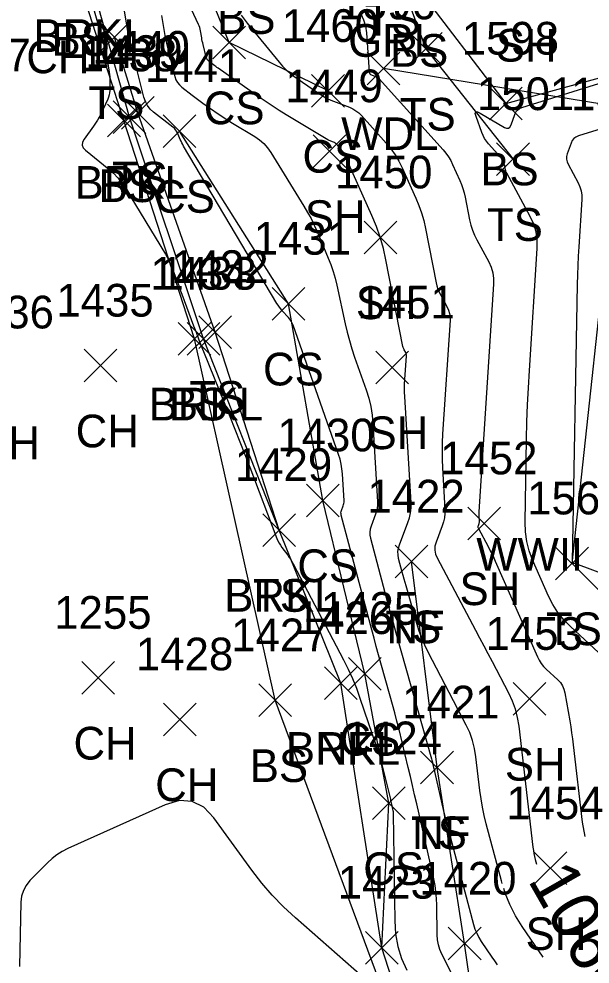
# Model space of a CAD drawing. Extents: x 1592612 to 1596497, y 111838 to 113741.
# Drawn here: x 1592890.9 to 1592925.8, y 113362.1 to 113419.9 of the extents above; entities that cross this region are included whole.
import ezdxf

# ---------------------------------------------------------------- set-up
doc = ezdxf.new("R2010")
doc.units = 0
for name, color, linetype in [('L_A', 7, 'Continuous'), ('L_C', 7, 'Continuous'), ('L_I', 7, 'Continuous'), ('L_TIC', 7, 'Continuous'), ('LAWA', 7, 'Continuous'), ('LAWE', 7, 'Continuous'), ('LELB', 7, 'Continuous'), ('LSOGCMA', 7, 'Continuous'), ('LSOGCMA_T', 7, 'Continuous'), ('LSOGCMI', 7, 'Continuous'), ('R_A', 7, 'Continuous')]:
    doc.layers.add(name, color=color, linetype=linetype)

msp = doc.modelspace()

# ---------------------------------------------------------------- linework, layer by layer
at = {"layer": 'L_TIC'}
for points in [[(1592895.764, 113417.792), (1592897.764, 113419.792)], [(1592897.764, 113417.792), (1592895.764, 113419.792)], [(1592902.782, 113417.472), (1592904.782, 113419.472)], [(1592904.782, 113417.472), (1592902.782, 113419.472)], [(1592914.797, 113417.084), (1592916.797, 113419.084)], [(1592916.797, 113417.084), (1592914.797, 113419.084)], [(1592912.205, 113415.891), (1592914.205, 113417.891)], [(1592914.205, 113415.891), (1592912.205, 113417.891)], [(1592908.817, 113414.507), (1592910.817, 113416.507)], [(1592910.817, 113414.507), (1592908.817, 113416.507)], [(1592897.198, 113413.176), (1592899.198, 113415.176)], [(1592899.198, 113413.176), (1592897.198, 113415.176)], [(1592919.685, 113413.734), (1592921.685, 113415.734)], [(1592921.685, 113413.734), (1592919.685, 113415.734)], [(1592896.345, 113412.71), (1592898.345, 113414.71)], [(1592898.345, 113412.71), (1592896.345, 113414.71)], [(1592896.68, 113412.914), (1592898.68, 113414.914)], [(1592898.68, 113412.914), (1592896.68, 113414.914)], [(1592899.746, 113412.057), (1592901.746, 113414.057)], [(1592901.746, 113412.057), (1592899.746, 113414.057)], [(1592908.914, 113410.819), (1592910.914, 113412.819)], [(1592910.914, 113410.819), (1592908.914, 113412.819)], [(1592920.128, 113410.337), (1592922.128, 113412.337)], [(1592922.128, 113410.337), (1592920.128, 113412.337)], [(1592912.03, 113405.547), (1592914.03, 113407.547)], [(1592914.03, 113405.547), (1592912.03, 113407.547)], [(1592906.403, 113401.492), (1592908.403, 113403.492)], [(1592908.403, 113401.492), (1592906.403, 113403.492)], [(1592900.65, 113399.349), (1592902.65, 113401.349)], [(1592902.65, 113399.349), (1592900.65, 113401.349)], [(1592901.208, 113399.349), (1592903.208, 113401.349)], [(1592903.208, 113399.349), (1592901.208, 113401.349)], [(1592901.926, 113399.759), (1592903.926, 113401.759)], [(1592903.926, 113399.759), (1592901.926, 113401.759)], [(1592894.902, 113397.704), (1592896.902, 113399.704)], [(1592896.902, 113397.704), (1592894.902, 113399.704)], [(1592912.742, 113397.594), (1592914.742, 113399.594)], [(1592914.742, 113397.594), (1592912.742, 113399.594)], [(1592908.499, 113389.458), (1592910.499, 113391.458)], [(1592910.499, 113389.458), (1592908.499, 113391.458)], [(1592918.367, 113388.051), (1592920.367, 113390.051)], [(1592920.367, 113388.051), (1592918.367, 113390.051)], [(1592905.825, 113387.644), (1592907.825, 113389.644)], [(1592907.825, 113387.644), (1592905.825, 113389.644)], [(1592905.825, 113387.644), (1592907.825, 113389.644)], [(1592907.825, 113387.644), (1592905.825, 113389.644)], [(1592913.915, 113385.717), (1592915.915, 113387.717)], [(1592915.915, 113385.717), (1592913.915, 113387.717)], [(1592913.915, 113385.717), (1592915.915, 113387.717)], [(1592915.915, 113385.717), (1592913.915, 113387.717)], [(1592923.735, 113385.602), (1592925.735, 113387.602)], [(1592925.735, 113385.602), (1592923.735, 113387.602)], [(1592894.773, 113378.603), (1592896.773, 113380.603)], [(1592896.773, 113378.603), (1592894.773, 113380.603)], [(1592911.075, 113378.848), (1592913.075, 113380.848)], [(1592913.075, 113378.848), (1592911.075, 113380.848)], [(1592909.596, 113378.281), (1592911.596, 113380.281)], [(1592911.596, 113378.281), (1592909.596, 113380.281)], [(1592909.596, 113378.281), (1592911.596, 113380.281)], [(1592911.596, 113378.281), (1592909.596, 113380.281)], [(1592921.14, 113377.314), (1592923.14, 113379.314)], [(1592923.14, 113377.314), (1592921.14, 113379.314)], [(1592905.593, 113377.229), (1592907.593, 113379.229)], [(1592907.593, 113377.229), (1592905.593, 113379.229)], [(1592899.766, 113376.061), (1592901.766, 113378.061)], [(1592901.766, 113376.061), (1592899.766, 113378.061)], [(1592915.481, 113373.12), (1592917.481, 113375.12)], [(1592917.481, 113373.12), (1592915.481, 113375.12)], [(1592915.481, 113373.12), (1592917.481, 113375.12)], [(1592917.481, 113373.12), (1592915.481, 113375.12)], [(1592912.529, 113370.926), (1592914.529, 113372.926)], [(1592914.529, 113370.926), (1592912.529, 113372.926)], [(1592922.41, 113366.949), (1592924.41, 113368.949)], [(1592924.41, 113366.949), (1592922.41, 113368.949)], [(1592917.171, 113362.34), (1592919.171, 113364.34)], [(1592919.171, 113362.34), (1592917.171, 113364.34)], [(1592912.1, 113362.091), (1592914.1, 113364.091)], [(1592914.1, 113362.091), (1592912.1, 113364.091)], [(1592912.1, 113362.091), (1592914.1, 113364.091)], [(1592914.1, 113362.091), (1592912.1, 113364.091)]]:
    msp.add_lwpolyline(points, dxfattribs=at)
at = {"layer": 'LAWA'}
msp.add_lwpolyline([(1592932.916, 113413.656), (1592913.205, 113416.891)], dxfattribs=at)
at = {"layer": 'LAWE'}
msp.add_lwpolyline([(1593001.92, 113269.875), (1592980.168, 113281.757), (1592972.077, 113292.77), (1592952.739, 113309.006), (1592930.405, 113333.014), (1592916.015, 113354.051), (1592913.1, 113363.091), (1592910.596, 113379.281), (1592906.825, 113388.644), (1592902.208, 113400.349), (1592897.68, 113413.914), (1592895.157, 113422.89), (1592891.073, 113425.248), (1592889.456, 113425.542), (1592888.74, 113438.019), (1592887.745, 113444.76), (1592887.496, 113453.354)], dxfattribs=at)
at = {"layer": 'LELB'}
for points in [[(1592909.817, 113415.507), (1592903.782, 113418.472), (1592899.758, 113428.347), (1592891.065, 113434.312)], [(1592908.536, 113430.778), (1592913.657, 113423.892), (1592915.797, 113418.084), (1592921.128, 113411.337)], [(1593000.607, 113268.02), (1592979.237, 113281.269), (1592969.817, 113290.666), (1592952.505, 113308.706), (1592930.32, 113332.83), (1592915.558, 113354.032), (1592906.593, 113378.229), (1592901.651, 113400.349), (1592897.345, 113413.71), (1592894.471, 113422.658), (1592891.543, 113424.972)], [(1592915.162, 113421.985), (1592920.685, 113414.734), (1592932.512, 113417.98), (1592943.04, 113416.389)], [(1592906.825, 113388.644), (1592902.926, 113400.759), (1592898.198, 113414.176), (1592896.764, 113418.792)], [(1593022.223, 113298.621), (1592996.05, 113319.251), (1592973.737, 113329.884), (1592951.567, 113338.734), (1592939.58, 113363.449), (1592930.763, 113371.375), (1592929.879, 113381.446), (1592924.735, 113386.602), (1592927.418, 113411.322), (1592932.961, 113414.131), (1592945.073, 113412.416), (1592963.598, 113404.825), (1592977.398, 113399.854), (1592996.446, 113393.062), (1593007.402, 113387.97)], [(1592913.1, 113363.091), (1592913.529, 113371.926), (1592912.075, 113379.848), (1592909.499, 113390.459), (1592907.403, 113402.492), (1592900.746, 113413.057)], [(1593002.844, 113271.334), (1592982.233, 113284.253), (1592973.366, 113294.033), (1592954.604, 113311.113), (1592933.333, 113334.792), (1592919.468, 113354.266), (1592918.171, 113363.34), (1592916.481, 113374.12), (1592914.915, 113386.717)]]:
    msp.add_lwpolyline(points, dxfattribs=at)
at = {"layer": 'LSOGCMA'}
for points in [[(1592904.499, 113420.148), (1592904.88, 113419.661), (1592906.836, 113417.26), (1592907.038, 113417.027), (1592907.255, 113416.811), (1592907.487, 113416.609), (1592907.733, 113416.423), (1592909.113, 113415.451), (1592909.182, 113415.403), (1592909.253, 113415.357), (1592909.324, 113415.311), (1592909.396, 113415.267), (1592909.685, 113415.093), (1592909.759, 113415.052), (1592909.833, 113415.013), (1592909.91, 113414.978), (1592909.988, 113414.946), (1592911.122, 113414.509), (1592911.329, 113414.415), (1592911.522, 113414.299), (1592911.699, 113414.161), (1592911.861, 113414.001), (1592913.378, 113412.319), (1592913.667, 113411.972), (1592913.927, 113411.605), (1592914.157, 113411.22), (1592914.358, 113410.815), (1592915.19, 113408.958), (1592915.378, 113408.506), (1592915.538, 113408.045), (1592915.672, 113407.576), (1592915.78, 113407.099), (1592916.43, 113403.778), (1592916.477, 113403.577), (1592916.54, 113403.381), (1592916.617, 113403.19), (1592916.708, 113403.005), (1592917.105, 113402.274), (1592917.19, 113402.088), (1592917.247, 113401.896), (1592917.276, 113401.698), (1592917.277, 113401.494), (1592916.822, 113394.504), (1592916.797, 113393.993), (1592916.788, 113393.481), (1592916.794, 113392.97), (1592916.816, 113392.458), (1592916.966, 113389.919), (1592916.968, 113389.656), (1592916.942, 113389.398), (1592916.888, 113389.143), (1592916.806, 113388.893), (1592916.423, 113387.902), (1592916.355, 113387.656), (1592916.342, 113387.414), (1592916.384, 113387.174), (1592916.481, 113386.938), (1592918.834, 113382.523), (1592919.088, 113382.044), (1592919.341, 113381.566), (1592919.593, 113381.087), (1592919.844, 113380.607), (1592920.846, 113378.687), (1592921.073, 113378.2), (1592921.254, 113377.698), (1592921.387, 113377.182), (1592921.474, 113376.652), (1592922.347, 113369.232), (1592922.373, 113369.045), (1592922.405, 113368.859), (1592922.443, 113368.674), (1592922.489, 113368.491), (1592922.563, 113368.21)], [(1592912.412, 113360.878), (1592907.821, 113364.914), (1592907.097, 113365.588), (1592906.413, 113366.298), (1592905.77, 113367.046), (1592905.167, 113367.83), (1592902.839, 113371.042), (1592902.217, 113371.694), (1592901.514, 113372.043), (1592900.73, 113372.09), (1592899.866, 113371.834), (1592893.905, 113369.151), (1592893.566, 113368.979), (1592893.247, 113368.778), (1592892.949, 113368.548), (1592892.671, 113368.289), (1592891.599, 113367.193), (1592891.364, 113366.906), (1592891.193, 113366.591), (1592891.087, 113366.249), (1592891.045, 113365.88), (1592890.951, 113361.938)]]:
    msp.add_lwpolyline(points, dxfattribs=at)
at = {"layer": 'LSOGCMI'}
for points in [[(1592920.473, 113367.017), (1592920.424, 113367.173), (1592919.494, 113370.672), (1592919.37, 113371.175), (1592919.264, 113371.681), (1592919.176, 113372.191), (1592919.106, 113372.705), (1592918.864, 113374.766), (1592918.781, 113375.274), (1592918.653, 113375.769), (1592918.48, 113376.249), (1592918.262, 113376.716), (1592915.938, 113381.17), (1592915.731, 113381.593), (1592915.546, 113382.026), (1592915.384, 113382.467), (1592915.244, 113382.918), (1592914.591, 113385.228), (1592914.533, 113385.438), (1592914.475, 113385.648), (1592914.417, 113385.858), (1592914.361, 113386.069), (1592914.137, 113386.911), (1592914.097, 113387.121), (1592914.092, 113387.329), (1592914.12, 113387.535), (1592914.182, 113387.739), (1592914.706, 113389.096), (1592914.803, 113389.392), (1592914.867, 113389.694), (1592914.898, 113390), (1592914.896, 113390.312), (1592914.512, 113396.824), (1592914.5, 113397.083), (1592914.497, 113397.341), (1592914.502, 113397.599), (1592914.515, 113397.857), (1592914.609, 113399.305), (1592914.609, 113399.355), (1592914.601, 113399.404), (1592914.588, 113399.451), (1592914.567, 113399.497), (1592914.469, 113399.676), (1592914.447, 113399.721), (1592914.428, 113399.768), (1592914.413, 113399.816), (1592914.401, 113399.865), (1592913.36, 113405.182), (1592913.204, 113405.875), (1592913.009, 113406.556), (1592912.776, 113407.225), (1592912.504, 113407.881), (1592910.832, 113411.611), (1592910.791, 113411.695), (1592910.743, 113411.775), (1592910.689, 113411.85), (1592910.629, 113411.922), (1592910.316, 113412.27), (1592910.283, 113412.303), (1592910.246, 113412.331), (1592910.206, 113412.355), (1592910.163, 113412.375), (1592909.985, 113412.443), (1592909.941, 113412.461), (1592909.898, 113412.481), (1592909.856, 113412.503), (1592909.815, 113412.527), (1592907.267, 113414.056), (1592906.831, 113414.323), (1592906.401, 113414.597), (1592905.975, 113414.88), (1592905.555, 113415.17), (1592903.096, 113416.901), (1592903.027, 113416.951), (1592902.957, 113417.001), (1592902.889, 113417.053), (1592902.821, 113417.105), (1592902.55, 113417.315), (1592902.488, 113417.371), (1592902.438, 113417.435), (1592902.4, 113417.507), (1592902.373, 113417.586), (1592902.181, 113418.341), (1592902.156, 113418.444), (1592902.133, 113418.548), (1592902.113, 113418.652), (1592902.095, 113418.757), (1592902.028, 113419.177), (1592902.008, 113419.281), (1592901.98, 113419.383), (1592901.946, 113419.483), (1592901.905, 113419.58), (1592898.668, 113426.542)], [(1592894.91, 113422.601), (1592896.168, 113418.115), (1592896.213, 113417.944), (1592896.253, 113417.773), (1592896.289, 113417.601), (1592896.319, 113417.427), (1592896.442, 113416.661), (1592896.461, 113416.522), (1592896.474, 113416.382), (1592896.481, 113416.242), (1592896.482, 113416.102), (1592896.473, 113415.539), (1592896.464, 113415.401), (1592896.44, 113415.265), (1592896.402, 113415.133), (1592896.349, 113415.004), (1592895.923, 113414.097), (1592895.827, 113413.906), (1592895.723, 113413.72), (1592895.611, 113413.539), (1592895.49, 113413.363), (1592894.909, 113412.56), (1592894.81, 113412.374), (1592894.792, 113412.199), (1592894.855, 113412.034), (1592894.998, 113411.879), (1592896.417, 113410.728), (1592896.702, 113410.475), (1592896.962, 113410.201), (1592897.198, 113409.906), (1592897.409, 113409.589), (1592899.875, 113405.524), (1592899.985, 113405.333), (1592900.086, 113405.137), (1592900.178, 113404.938), (1592900.261, 113404.733), (1592900.574, 113403.907), (1592900.652, 113403.7), (1592900.729, 113403.494), (1592900.806, 113403.287), (1592900.883, 113403.08), (1592901.602, 113401.135), (1592901.749, 113400.743), (1592901.898, 113400.351), (1592902.051, 113399.961), (1592902.206, 113399.572), (1592903.814, 113395.59), (1592904.123, 113394.818), (1592904.429, 113394.044), (1592904.731, 113393.27), (1592905.029, 113392.493), (1592906.698, 113388.117), (1592906.757, 113387.976), (1592906.826, 113387.841), (1592906.904, 113387.711), (1592906.992, 113387.586), (1592907.361, 113387.098), (1592907.451, 113386.974), (1592907.535, 113386.847), (1592907.614, 113386.717), (1592907.688, 113386.583), (1592910.763, 113380.709), (1592911.049, 113380.136), (1592911.313, 113379.554), (1592911.554, 113378.962), (1592911.772, 113378.36), (1592912.791, 113375.378), (1592912.9, 113375.049), (1592913, 113374.717), (1592913.093, 113374.384), (1592913.178, 113374.048), (1592913.629, 113372.18), (1592913.647, 113372.104), (1592913.665, 113372.028), (1592913.683, 113371.951), (1592913.7, 113371.875), (1592913.769, 113371.57), (1592913.784, 113371.493), (1592913.795, 113371.416), (1592913.803, 113371.339), (1592913.806, 113371.261), (1592913.895, 113364.728), (1592913.949, 113363.94), (1592914.091, 113363.174), (1592914.32, 113362.429), (1592914.637, 113361.706)], [(1592917.351, 113361.582), (1592916.786, 113362.699), (1592916.662, 113362.983), (1592916.572, 113363.275), (1592916.516, 113363.575), (1592916.495, 113363.884), (1592916.47, 113365.694), (1592916.454, 113366.099), (1592916.417, 113366.501), (1592916.359, 113366.901), (1592916.28, 113367.298), (1592915.239, 113371.893), (1592915.112, 113372.451), (1592914.982, 113373.008), (1592914.851, 113373.565), (1592914.718, 113374.122), (1592914.16, 113376.433), (1592914.034, 113376.945), (1592913.903, 113377.456), (1592913.767, 113377.965), (1592913.626, 113378.474), (1592913.053, 113380.504), (1592912.91, 113381.012), (1592912.77, 113381.521), (1592912.631, 113382.03), (1592912.495, 113382.539), (1592910.625, 113389.561), (1592910.612, 113389.634), (1592910.61, 113389.706), (1592910.619, 113389.778), (1592910.641, 113389.849), (1592910.75, 113390.131), (1592910.773, 113390.202), (1592910.789, 113390.275), (1592910.796, 113390.348), (1592910.796, 113390.423), (1592910.698, 113392.085), (1592910.67, 113392.385), (1592910.621, 113392.68), (1592910.551, 113392.972), (1592910.461, 113393.26), (1592907.678, 113401.18), (1592907.626, 113401.309), (1592907.562, 113401.43), (1592907.486, 113401.544), (1592907.399, 113401.651), (1592907.025, 113402.066), (1592906.935, 113402.172), (1592906.849, 113402.282), (1592906.77, 113402.396), (1592906.696, 113402.514), (1592900.992, 113412.127), (1592900.935, 113412.225), (1592900.883, 113412.325), (1592900.833, 113412.427), (1592900.787, 113412.531), (1592900.609, 113412.948), (1592900.559, 113413.048), (1592900.497, 113413.139), (1592900.424, 113413.222), (1592900.341, 113413.296), (1592899.159, 113414.214), (1592898.952, 113414.403), (1592898.783, 113414.617), (1592898.654, 113414.857), (1592898.564, 113415.123), (1592897.837, 113417.986), (1592897.744, 113418.37), (1592897.66, 113418.756), (1592897.585, 113419.143), (1592897.518, 113419.532), (1592897.238, 113421.281)], [(1592899.648, 113420.135), (1592899.807, 113419.145), (1592899.849, 113418.898), (1592899.897, 113418.652), (1592899.95, 113418.407), (1592900.009, 113418.163), (1592900.461, 113416.385), (1592900.524, 113416.198), (1592900.615, 113416.029), (1592900.733, 113415.878), (1592900.879, 113415.745), (1592901.517, 113415.25), (1592901.677, 113415.127), (1592901.839, 113415.006), (1592902.002, 113414.887), (1592902.166, 113414.769), (1592903.107, 113414.107), (1592903.32, 113413.96), (1592903.535, 113413.817), (1592903.753, 113413.678), (1592903.974, 113413.543), (1592905.349, 113412.717), (1592905.637, 113412.521), (1592905.896, 113412.294), (1592906.126, 113412.037), (1592906.326, 113411.751), (1592908.349, 113408.457), (1592908.571, 113408.08), (1592908.778, 113407.696), (1592908.97, 113407.303), (1592909.146, 113406.903), (1592909.823, 113405.288), (1592909.982, 113404.881), (1592910.123, 113404.468), (1592910.245, 113404.049), (1592910.348, 113403.624), (1592910.865, 113401.262), (1592910.986, 113400.746), (1592911.123, 113400.233), (1592911.276, 113399.725), (1592911.444, 113399.222), (1592912.148, 113397.217), (1592912.306, 113396.712), (1592912.428, 113396.2), (1592912.514, 113395.68), (1592912.563, 113395.153), (1592912.846, 113390.368), (1592912.847, 113390.174), (1592912.828, 113389.984), (1592912.788, 113389.797), (1592912.728, 113389.613), (1592912.446, 113388.884), (1592912.391, 113388.701), (1592912.366, 113388.517), (1592912.371, 113388.33), (1592912.406, 113388.142), (1592913.291, 113384.818), (1592913.456, 113384.201), (1592913.624, 113383.585), (1592913.794, 113382.969), (1592913.967, 113382.355), (1592916.146, 113374.638), (1592916.163, 113374.574), (1592916.181, 113374.509), (1592916.197, 113374.445), (1592916.213, 113374.38), (1592916.276, 113374.12), (1592916.291, 113374.056), (1592916.306, 113373.991), (1592916.322, 113373.926), (1592916.336, 113373.861), (1592916.781, 113371.898), (1592916.862, 113371.55), (1592916.945, 113371.202), (1592917.032, 113370.855), (1592917.123, 113370.509), (1592918.718, 113364.508), (1592918.803, 113364.234), (1592918.91, 113363.971), (1592919.039, 113363.718), (1592919.189, 113363.474), (1592919.834, 113362.52), (1592919.994, 113362.281), (1592920.151, 113362.04)], [(1592911.815, 113420.226), (1592911.991, 113419.862), (1592912.108, 113419.476), (1592912.167, 113419.066), (1592912.338, 113416.676), (1592912.35, 113416.614), (1592912.376, 113416.562), (1592912.418, 113416.522), (1592912.473, 113416.492), (1592912.726, 113416.395), (1592912.787, 113416.368), (1592912.843, 113416.334), (1592912.895, 113416.293), (1592912.942, 113416.246), (1592916.858, 113411.904), (1592917.029, 113411.699), (1592917.182, 113411.482), (1592917.319, 113411.254), (1592917.437, 113411.015), (1592917.877, 113410.034), (1592917.979, 113409.787), (1592918.067, 113409.535), (1592918.141, 113409.278), (1592918.2, 113409.017), (1592918.474, 113407.617), (1592918.548, 113407.3), (1592918.646, 113406.991), (1592918.767, 113406.691), (1592918.912, 113406.399), (1592919.644, 113405.051), (1592919.793, 113404.725), (1592919.893, 113404.389), (1592919.943, 113404.041), (1592919.944, 113403.682), (1592919.039, 113389.753), (1592919.036, 113389.687), (1592919.035, 113389.622), (1592919.035, 113389.556), (1592919.038, 113389.49), (1592919.058, 113389.163), (1592919.058, 113389.129), (1592919.055, 113389.096), (1592919.048, 113389.063), (1592919.037, 113389.031), (1592918.988, 113388.903), (1592918.979, 113388.871), (1592918.977, 113388.84), (1592918.983, 113388.809), (1592918.995, 113388.779), (1592919.63, 113387.587), (1592919.74, 113387.377), (1592919.845, 113387.165), (1592919.946, 113386.952), (1592920.044, 113386.736), (1592922.617, 113380.894), (1592922.724, 113380.682), (1592922.85, 113380.484), (1592922.996, 113380.3), (1592923.162, 113380.13), (1592923.867, 113379.481), (1592924.026, 113379.309), (1592924.152, 113379.119), (1592924.243, 113378.911), (1592924.301, 113378.684), (1592924.596, 113376.967), (1592924.656, 113376.602), (1592924.711, 113376.236), (1592924.761, 113375.869), (1592924.807, 113375.502), (1592925.359, 113370.776), (1592925.516, 113369.895)], [(1592926.35, 113381.157), (1592924.632, 113382.741), (1592924.227, 113383.154), (1592923.871, 113383.602), (1592923.563, 113384.084), (1592923.303, 113384.602), (1592922.323, 113386.825), (1592922.113, 113387.38), (1592921.966, 113387.948), (1592921.882, 113388.528), (1592921.862, 113389.122), (1592921.953, 113394.212), (1592921.978, 113395.26), (1592922.015, 113396.308), (1592922.065, 113397.355), (1592922.127, 113398.401), (1592922.612, 113405.871), (1592922.611, 113406.384), (1592922.538, 113406.881), (1592922.396, 113407.363), (1592922.182, 113407.829), (1592920.743, 113410.479), (1592920.718, 113410.53), (1592920.697, 113410.582), (1592920.68, 113410.636), (1592920.667, 113410.691), (1592920.619, 113410.934), (1592920.609, 113410.979), (1592920.596, 113411.024), (1592920.581, 113411.068), (1592920.563, 113411.111), (1592920.487, 113411.281), (1592920.466, 113411.323), (1592920.442, 113411.362), (1592920.416, 113411.4), (1592920.386, 113411.435), (1592919.627, 113412.278), (1592919.498, 113412.435), (1592919.387, 113412.602), (1592919.293, 113412.779), (1592919.216, 113412.967), (1592918.868, 113413.947), (1592918.823, 113414.13), (1592918.851, 113414.226), (1592918.95, 113414.235), (1592919.122, 113414.156), (1592920.603, 113413.281), (1592920.738, 113413.225), (1592920.852, 113413.231), (1592920.942, 113413.299), (1592921.01, 113413.43), (1592921.237, 113414.075), (1592921.307, 113414.222), (1592921.403, 113414.342), (1592921.526, 113414.434), (1592921.676, 113414.499), (1592932.392, 113417.85)], [(1592928.756, 113413.892), (1592925.127, 113412.757), (1592924.974, 113412.69), (1592924.847, 113412.596), (1592924.748, 113412.473), (1592924.676, 113412.321), (1592924.444, 113411.66), (1592924.404, 113411.496), (1592924.399, 113411.335), (1592924.429, 113411.176), (1592924.495, 113411.021), (1592925.108, 113409.892), (1592925.22, 113409.649), (1592925.294, 113409.397), (1592925.332, 113409.138), (1592925.333, 113408.87), (1592925.144, 113405.973), (1592925.111, 113405.399), (1592925.083, 113404.825), (1592925.063, 113404.251), (1592925.049, 113403.677), (1592924.744, 113386.698), (1592924.744, 113386.692), (1592924.746, 113386.685), (1592924.748, 113386.679), (1592924.75, 113386.673), (1592924.769, 113386.642), (1592924.772, 113386.636), (1592924.774, 113386.629), (1592924.776, 113386.627), (1592924.778, 113386.626), (1592924.874, 113386.62), (1592924.89, 113386.618), (1592924.907, 113386.615), (1592924.923, 113386.611), (1592924.938, 113386.606), (1592931.666, 113384.097)], [(1592922.965, 113362.507), (1592921.693, 113364.387), (1592921.288, 113365.043), (1592920.941, 113365.726), (1592920.653, 113366.436), (1592920.57, 113366.705)]]:
    msp.add_lwpolyline(points, dxfattribs=at)

# ---------------------------------------------------------------- texts
at = {"layer": 'L_A'}
for s, p in [('BS', (1592903.037, 113419.002)), ('TS', (1592912.066, 113418.892)), ('BRKL', (1592891.803, 113417.89)), ('BS', (1592892.912, 113417.658)), ('SH', (1592920.077, 113417.304)), ('BS', (1592913.603, 113416.986)), ('CH', (1592891.374, 113416.595)), ('TS', (1592895.173, 113413.792)), ('CS', (1592902.223, 113413.472)), ('TS', (1592914.206, 113413.084)), ('WDL', (1592910.623, 113411.891)), ('CS', (1592908.258, 113410.507)), ('BS', (1592919.126, 113409.734)), ('TS', (1592896.608, 113409.176)), ('BRKL', (1592894.326, 113408.914)), ('BS', (1592895.786, 113408.71)), ('CS', (1592899.187, 113408.057)), ('SH', (1592908.402, 113406.819)), ('TS', (1592919.537, 113406.337)), ('SH', (1592911.518, 113401.547)), ('CS', (1592905.844, 113397.492)), ('BRKL', (1592898.854, 113395.349)), ('BS', (1592900.091, 113395.349)), ('TS', (1592901.335, 113395.759)), ('CH', (1592894.391, 113393.704)), ('SH', (1592912.23, 113393.594)), ('CH', (1592888.347, 113392.98)), ('CS', (1592907.94, 113385.458)), ('TS', (1592905.235, 113383.644)), ('SH', (1592917.855, 113384.051)), ('BRKL', (1592903.471, 113383.644)), ('TS', (1592913.325, 113381.717)), ('NF', (1592913.396, 113381.717)), ('TS', (1592923.144, 113381.602)), ('CH', (1592894.261, 113374.603)), ('CS', (1592910.516, 113374.848)), ('BRKL', (1592907.241, 113374.281)), ('NF', (1592909.076, 113374.281)), ('SH', (1592920.628, 113373.314)), ('BS', (1592905.034, 113373.229)), ('CH', (1592899.254, 113372.061)), ('TS', (1592914.891, 113369.12)), ('NF', (1592914.962, 113369.12)), ('CS', (1592911.97, 113366.926)), ('SH', (1592921.899, 113362.949))]:
    msp.add_text(s, height=2, dxfattribs=at).set_placement(p)
at = {"layer": 'L_C'}
msp.add_text("WWII PLAQUE 1.0' X 2.0'", height=2, dxfattribs=at).set_placement((1592918.88, 113386.161))
at = {"layer": 'L_I'}
for s, p in [('1596', (1592910.457, 113419.891)), ('1460', (1592906.99, 113418.507)), ('1598', (1592917.992, 113417.734)), ('1437', (1592885.697, 113416.708)), ('1438', (1592894.652, 113416.71)), ('1439', (1592894.979, 113416.914)), ('1440', (1592895.419, 113417.176)), ('1441', (1592898.62, 113416.057)), ('1449', (1592907.213, 113414.819)), ('1501', (1592918.923, 113414.337)), ('1567', (1592924.678, 113414.321)), ('1450', (1592910.25, 113409.547)), ('1431', (1592905.277, 113405.492)), ('1434', (1592898.958, 113403.349)), ('1433', (1592899.516, 113403.349)), ('1432', (1592900.233, 113403.759)), ('1435', (1592893.21, 113401.704)), ('1451', (1592911.616, 113401.594)), ('1436', (1592887.111, 113400.98)), ('1430', (1592906.719, 113393.458)), ('1452', (1592916.674, 113392.051)), ('1429', (1592904.124, 113391.644)), ('1429', (1592904.124, 113391.644)), ('1422', (1592912.222, 113389.717)), ('1422', (1592912.222, 113389.717)), ('1564', (1592921.995, 113389.602)), ('1255', (1592893.08, 113382.603)), ('1425', (1592909.382, 113382.848)), ('1426', (1592907.848, 113382.281)), ('1426', (1592907.848, 113382.281)), ('1427', (1592903.9, 113381.229)), ('1453', (1592919.447, 113381.314)), ('1428', (1592898.073, 113380.061)), ('1421', (1592914.355, 113377.12)), ('1421', (1592914.355, 113377.12)), ('1424', (1592910.836, 113374.926)), ('1454', (1592920.718, 113370.949)), ('1420', (1592915.392, 113366.34)), ('1423', (1592910.407, 113366.091)), ('1423', (1592910.407, 113366.091))]:
    msp.add_text(s, height=2, dxfattribs=at).set_placement(p)
at = {"layer": 'LSOGCMA_T'}
msp.add_text('1060', height=3, rotation=299.71155, dxfattribs=at).set_placement((1592921.995, 113367.233))
at = {"layer": 'R_A'}
msp.add_text('GRL', height=2, dxfattribs=at).set_placement((1592911.052, 113417.6))

doc.saveas('drawing.dxf')
